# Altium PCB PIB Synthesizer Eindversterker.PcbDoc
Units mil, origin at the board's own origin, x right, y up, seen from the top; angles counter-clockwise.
Board outline 5060 x 2930 mil, 2 copper layers (Top Layer, Bottom Layer); 32 components, 26 nets, 88 pads, 1 vias.
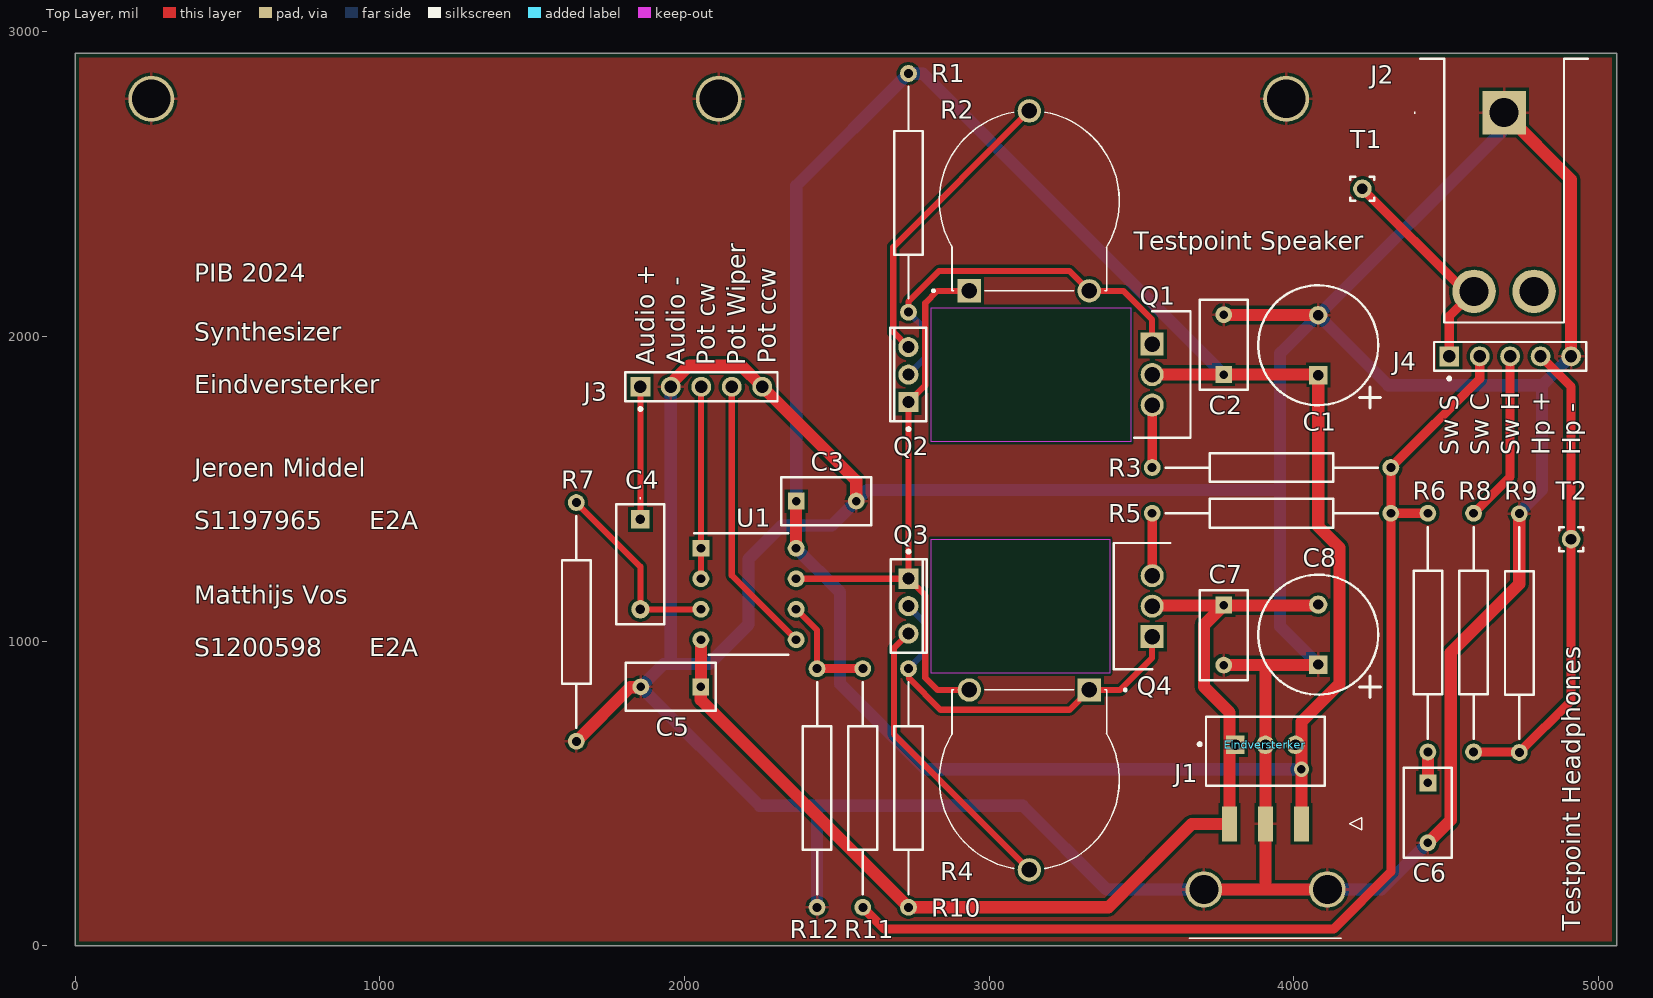
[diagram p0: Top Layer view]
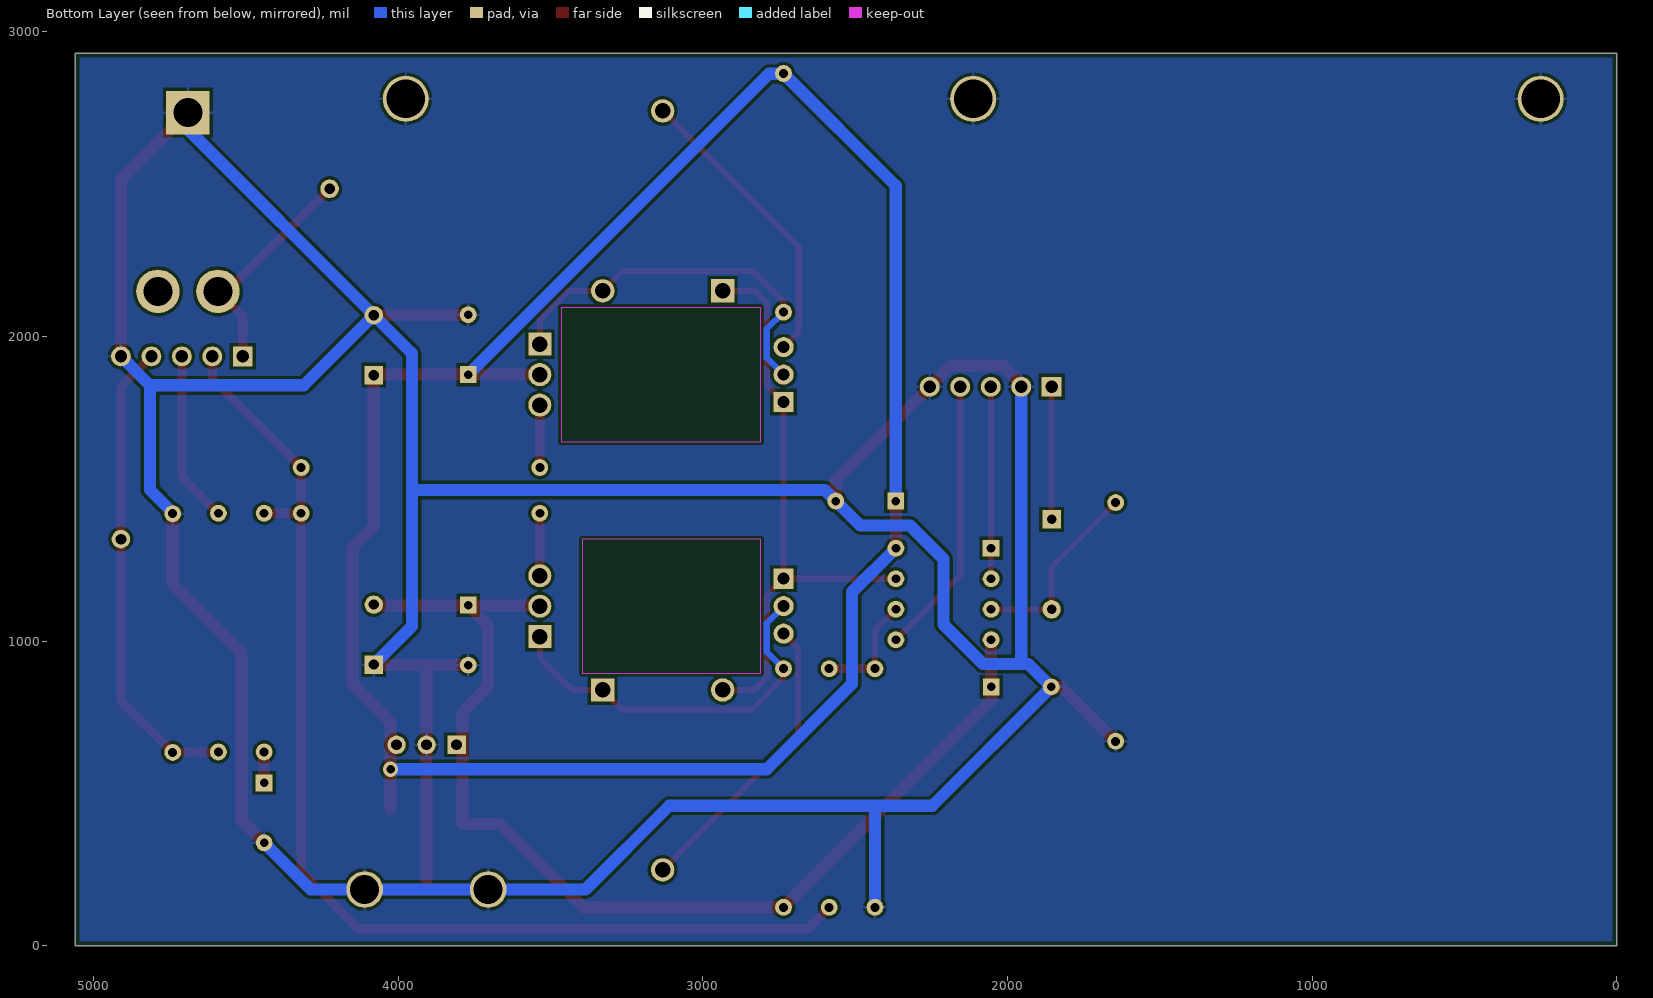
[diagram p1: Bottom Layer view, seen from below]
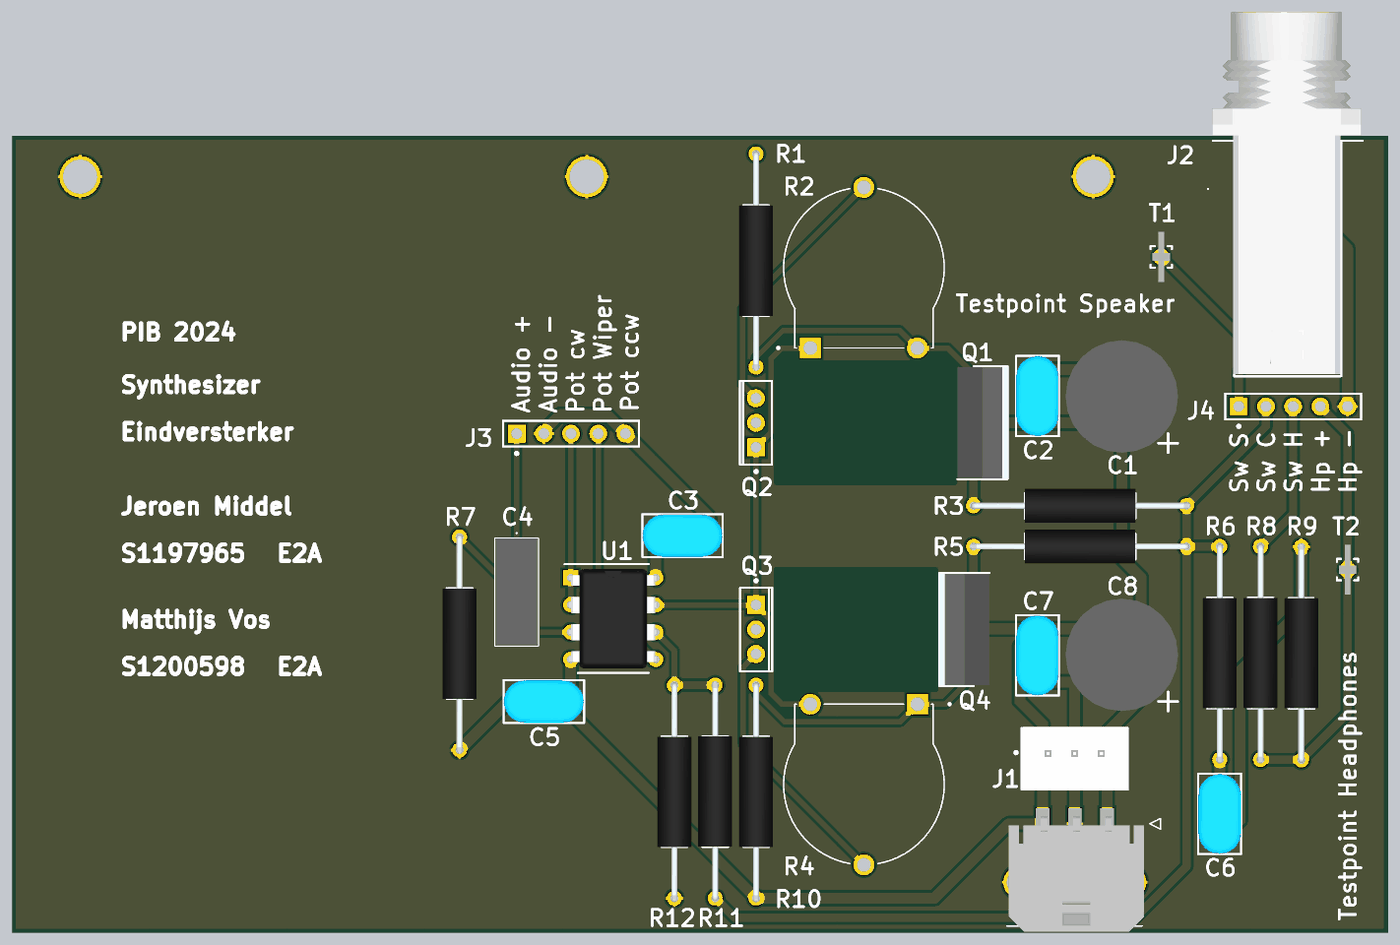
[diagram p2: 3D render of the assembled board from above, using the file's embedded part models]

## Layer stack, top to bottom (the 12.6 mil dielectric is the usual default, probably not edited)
Top Solder: solder mask 0.4, Solder Resist, Dk 3.5
Top Layer: signal copper 1.4
Dielectric 1: dielectric 12.6, FR-4, Dk 4.8
Bottom Layer: signal copper 1.4
Bottom Solder: solder mask 0.4, Solder Resist, Dk 3.5

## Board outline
0,0 0,2930 5060,2930 5060,0

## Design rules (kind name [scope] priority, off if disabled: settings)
BoardOutlineClearance "BoardOutlineClearance AISLER" [All] p1: gap=11.81 ignorepadtopadclearanceinfootprint=FALSE
Clearance [All] p1: gap=10 ignorepadtopadclearanceinfootprint=FALSE
Clearance "Clearance AISLER Simple" [All] p2: gap=5.91 ignorepadtopadclearanceinfootprint=FALSE except(0: Arc-Text Track-Text SMDPad-Text THPad-Text Via-Text Fill-Text Poly-Text Region-Text Text-Text Text-Hole; 7.87: Fill-Fill Fill-Poly Fill-Region Poly-Poly Poly-Region Region-Region; 9.84: Arc-Hole Track-Hole SMDPad-Hole THPad-Hole Via-Hole Fill-Hole Poly-Hole Region-Hole)
Height [All] p1: minheight=0 maxheight=3000 prefheight=500
HoleSize [All] p1: absolutevalues=TRUE maxlimit=220 minlimit=1 maxpercent=80.000 minpercent=20.000
HoleSize "HoleSize NPTH AISLER Simple" [PadIsPlated = 'False'] p2: absolutevalues=TRUE maxlimit=228.35 minlimit=11.81 maxpercent=80.000 minpercent=20.000
HoleSize "HoleSize PTH AISLER Simple" [All] p3: absolutevalues=TRUE maxlimit=222.44 minlimit=11.81 maxpercent=80.000 minpercent=20.000
HoleToHoleClearance "HoleToHoleClearance NPTH-NPTH AISLER" [PadIsPlated = 'False' vs PadIsPlated = 'False'] p2: gap=11.81 allowstackedmicrovias=FALSE // 0.25 + (0.05/2 + 0.05/2)
HoleToHoleClearance "HoleToHoleClearance NPTH-PTH AISLER" [PadIsPlated = 'False' vs PadIsPlated = 'True'] p3: gap=13.78 allowstackedmicrovias=FALSE // 0.25 + (0.05/2 + 0.15/2)
HoleToHoleClearance "HoleToHoleClearance Rest AISLER" [All] p4: gap=15.75 allowstackedmicrovias=FALSE // 0.25 + (0.15/2 + 0.15/2)
MinimumAnnularRing "MinimumAnnularRing AISLER" [IsVia] p1: minimumring=7.87
MinimumAnnularRing [All] p2: minimumring=12
MinimumSolderMaskSliver "MinimumSolderMaskSliver AISLER" [All] p2: minsoldermaskwidth=4.53 // AISLER enlarges all Solder Mask Openings by 20um by default, final Sliver is thus 0.075mm
PlaneClearance "PlaneClearance AISLER Simple" [All] p2: clearance=7.87
PolygonConnect [All] p1: connectstyle=Relief reliefconductorwidth=10 reliefentries=4 polygonreliefangle="90 Angle" airgapwidth=10
RoutingVias [All] p1: holewidth=28 width=50 viastyle="Through Hole" minholewidth=28 minwidth=50 maxholewidth=28 maxwidth=50
RoutingVias "RoutingVias AISLER Simple" [All] p2: holewidth=29.53 width=45.28 viastyle="Through Hole" minholewidth=11.81 minwidth=27.56 maxholewidth=39.37 maxwidth=55.12 // only minimum size relevant
SilkToSolderMaskClearance "SilkToSolderMaskClearance AISLER" [IsPad] p1: minsilkscreentomaskgap=5 clearancetoexposedcopper=TRUE
SolderMaskExpansion [All] p1: expansion=4 istentingtop=FALSE
Width [All] p1: maxlimit=40 minlimit=20 preferedwidth=40 minimp=50.000000 maximp=50.000000 favimp=50.000000
Width "Width AISLER Simple" [All] p2: maxlimit=59.06 minlimit=7.87 preferedwidth=19.68 // only min is relevant
27 further rules are at their usual default settings.

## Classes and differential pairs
component class "PIB Synthesizer Eindversterker": C1 C2 C3 C4 C5 C6 C7 C8 J1 J2 Q1 Q2 Q3 Q4 R1 R2 R3 R4 R5 R6 R7 R8 R9 R10 R11 R12 T1 T2 U1A U1B

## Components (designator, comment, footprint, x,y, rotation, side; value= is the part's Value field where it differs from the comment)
C1 "330uF" CAPPRD500W65D1000H2200 4080,1873.15 r90 top
C2 "100nF" FP-RDE4K1-MFG 3770,1973.43 r90 top
C3 "100nF" FP-RDE4K1-MFG 2465,1460 r0 top
C4 "470nF" MKS4C034702C00JSSD 1855,1400 r270 top
C5 "100nF" FP-RDE4K1-MFG 1955,850 r180 top
C6 "100nF" FP-RDE4K1-MFG 4440,436.57 r270 top
C7 "100nF" FP-RDE4K1-MFG 3770,1020 r270 top
C8 "330uF" CAPPRD500W65D1000H2200 4080,923.15 r90 top
Eindversterker "Comment" FP-B3B-XH-A_LF_SN-MFG 3906.57,639.33 r0 top
J1 "43650-0310" 43650-03YY_091011 3907.24,400.35 r0 top
J2 "speaker out" SJ63053A 4690,2735 r270 top
J3 "Comment" FCI-77311-5_V 2055,1835 r0 top
J4 "Comment" FCI-77311-5_V 4710,1935 r0 top
Q1 "IRF540N" TO254P469X1042X1967-3P 3535,1975 r270 top
Q2 "BD139" ONSC-TO-225-3-77-09 2735,1875 r180 top
Q3 "BD140" ONSC-TO-225-3-77-09 2735,1115 r0 top
Q4 "IRF9540N" TO254P469X1042X1967-3P 3535,1015 r90 top
R1 "2k2" RESAD1987W56L1031D239 2735,2080 r90 top
R2 "1k" TRIM_PTN15-E02SB20 3131.85,2445.28 r0 top
R3 "1" RESAD1987W56L1031D239 4318.46,1570 r180 top
R4 "1k" TRIM_PTN15-E02SB20 3131.85,544.72 r180 top
R5 "1" RESAD1987W56L1031D239 3535,1420 r0 top
R6 "10" RESAD1987W56L1031D239 4440,636.54 r90 top locked
R7 "68k" RESAD1987W56L1031D239 1645,671.54 r90 top
R8 "27" RESAD1987W56L1031D239 4590,636.54 r90 top
R9 "1" RESAD1987W56L1031D239 4740,1418.46 r270 top
R10 "2k2" RESAD1987W56L1031D239 2735,126.54 r90 top
R11 "2k2" RESAD1987W56L1031D239 2585,910 r270 top
R12 "1k" RESAD1987W56L1031D239 2435,126.54 r90 top
T1 "Testpoint Speaker" SAMTEC_MTMM-101-X-X-S-X 4225,2485 r0 top
T2 "Testpoint Headphones" SAMTEC_MTMM-101-X-X-S-X 4910,1335 r0 top
U1 "Comment" DIP794W53P254L959H508Q8N 2210,1155 r0 top

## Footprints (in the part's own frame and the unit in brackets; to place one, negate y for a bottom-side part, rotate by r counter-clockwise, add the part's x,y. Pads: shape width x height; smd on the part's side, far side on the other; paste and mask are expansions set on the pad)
43650-03YY_091011 [mm]
  rect 1.27x2.92 smd: 1(3,0) 2(0,0) 3(-3,0)
  round 3.062 hole 2.41: 4(5.15,-5.47) 5(-5.15,-5.47)
  silkscreen extent -6.36,-9.53 8,0.5, body extent -6.17,-10.06 6.47,0.68, height 5.71
CAPPRD500W65D1000H2200 [mm]
  rect 1.529x1.529 hole 0.85: 1(0,0)
  round 1.529 hole 0.85: 2(5,0)
  silkscreen extent -2.5,-5 7.5,5, body extent -2.75,-5.24 7.75,5.24, height 22
DIP794W53P254L959H508Q8N [mm]
  rect 1.409x1.409 hole 0.73: 1(-3.97,3.81)
  round 1.409 hole 0.73: 2(-3.97,1.27) 3(-3.97,-1.27) 4(-3.97,-3.81) 5(3.97,-3.81) 6(3.97,-1.27) 7(3.97,1.27) 8(3.97,3.81)
  silkscreen extent -4.53,-5.08 3.3,5.08, body extent -4.1,-4.64 4.1,4.64, height 4.21
FCI-77311-5_V [mm] "THD, 5-Leads, Body 12.7x2.4mm, Pitch 2.54mm"
  rect 1.652x1.652 hole 1.02: 1(-5.08,0)
  round 1.652 hole 1.02: 2(-2.54,0) 3(0,0) 4(2.54,0) 5(5.08,0)
  silkscreen extent -6.35,-1.97 6.35,1.2, body extent -6.35,-1.2 6.35,1.2, height 16.24
FP-B3B-XH-A_LF_SN-MFG [mm]
  rect 1.527x1.527 hole 0.9 paste-2539.97 mask+0: 1(-2.5,0.525)
  round 1.527 hole 0.9 paste-2539.97 mask+0: 2(0,0.525) 3(2.5,0.525)
  silkscreen extent -5.6,-2.88 4.95,2.88, body extent -5.05,-2.98 5.05,2.98, height 0.25
FP-RDE4K1-MFG [mm]
  rect 1.403x1.403 hole 0.7 paste-2539.97 mask+0: 1(-2.5,0)
  round 1.403 hole 0.7 paste-2539.97 mask+0: 2(2.5,0)
  silkscreen extent -3.75,-2 3.75,2, body extent -3.85,-2.1 3.85,2.1, height 0.25
MKS4C034702C00JSSD [mm]
  rect 1.529x1.529 hole 0.8: 1(0,0)
  round 1.529 hole 0.8: 2(7.5,0)
  silkscreen extent -1.8,-2 8.75,2, body extent -1.25,-2 8.75,2, height 9.1
ONSC-TO-225-3-77-09 [mm] "FM, 3-Leads, Body 7.8x3mm, Pitch 2.29mm"
  rect 1.676x1.676 hole 1: 1(0,2.29)
  round 1.676 hole 1: 2(0,0) 3(0,-2.29)
  silkscreen extent -1.49,-3.9 1.51,4.67, body extent -1.49,-3.9 1.51,3.9, height 13.64
RESAD1987W56L1031D239 [mm]
  round 1.404 hole 0.75: 1(0,0) 2(19.9,0)
  silkscreen extent 1.14,-1.19 18.8,1.19, body extent -0.28,-1.58 20.15,1.58, height 3.18
SAMTEC_MTMM-101-X-X-S-X [mm]
  round 1.545 hole 0.89: 01(0,0)
  silkscreen extent -1,-1 1,1
SJ63053A [mm]
  rect 3.63x3.63 hole 2.42: 1(0,0)
  round 3.63 hole 2.42: 2(14.9,-2.5) 3(14.9,2.5)
  silkscreen extent -4.5,-7.5 17.5,7, body extent -16.54,-7.04 17.31,6.86, height 13.32
TO254P469X1042X1967-3P [mm]
  rect 1.92x1.92 hole 1.28: 1(0,0)
  round 1.92 hole 1.28: 2(2.54,0) 3(5.08,0)
  silkscreen extent -2.73,-1.5 7.81,3.19, body extent -2.67,-1.5 7.75,3.19, height 18.84
TRIM_PTN15-E02SB20 [mm]
  rect 1.95x1.95 hole 1.3: 1(-5,-7.5)
  round 1.95 hole 1.3: 2(0,7.5) 3(5,-7.5)
  silkscreen extent -8.1,-7.6 7.5,7.39

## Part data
C1 C8: library part EEU-TP1V331B, "Capacitor Polarised", Manufacturer_Name=Panasonic, Mouser Part Number=667-EEU-TP1V331B
C2 C3 C5 C6 C7: library part CMP-06035-043861-1, "Ceramic Capacitor 47nF ±10% 1kV X7R Radial", Case/Package=Radial, Dielectric=X7R, Max Operating Temperature=125°C, Min Operating Temperature=-55°C, Package Quantity=500, Resistor Type=Ceramic, Tolerance=10%, Voltage Rating=1kV
C4: library part MKS4C034702C00JSSD, "Capacitor", Manufacturer_Name=WIMA, Mouser Part Number=505-MKS4C034702C00JS
J1: "Connector", Manufacturer_Name=Molex, Mouser Part Number=538-43650-0310
J2: library part SJ-63053A, "Connector", Manufacturer_Name="Same Sky", Mouser Part Number=490-SJ-63053A
Q1: "MOSFET (N-Channel)", Manufacturer_Name=Infineon
Q2: library part CMP-1048-01271-1, "Plastic Medium-Power Silicon NPN Transistor, 3-Pin TO-225, Bulk Box", Manufacturer="On Semiconductor"
Q3: library part CMP-1048-00039-1, "Plastic Medium-Power Silicon PNP Transistor, 3-Pin TO-225, Bulk Box", Manufacturer="On Semiconductor"
Q4: "MOSFET (P-Channel)", Manufacturer_Name=Infineon
R1 R3 R5 R6 R7 R8 R9 R10 R11 R12: library part RS01A1R000FE12, "Resistor", Manufacturer_Name=Vishay, Mouser Part Number=71-RS01A1R000FE12
R2 R4: library part PTN15-E02SB20, "15 mm, 2 kÎ©, Vertical, Linear, Screwdriver Shaftless Trimmer Potentiometer", Package=None
T1 T2: library part MTMM-101-X-X-S-X, "Connector Header Through Hole 1 position", Package=None

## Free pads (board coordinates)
  round 150.98 hole 125.98: 4(250,2780) 4(2112.5,2780) 4(3975,2780)

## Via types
v1: diameter 50, hole 28, Top Layer to Bottom Layer, 1 vias

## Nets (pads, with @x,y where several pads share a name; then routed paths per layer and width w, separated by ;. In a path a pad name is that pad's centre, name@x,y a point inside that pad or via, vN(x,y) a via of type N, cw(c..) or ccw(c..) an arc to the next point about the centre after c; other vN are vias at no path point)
+3v3: 
+5: 
+12: 
-12: 
-VCC: C5.1 C7.1 C8.2 Eindversterker.1 J1.3 Q4.2 R10.1 U1.4 | length 3644.7
  Top Layer w40: 2053.27,808.27 2053.43,808.11 ; C5.1 2053.43,808.11 ; C5.1@2053.7,850.28 U1.4 ; R10.1 2053.43,808.11 ; R10.1@2736.43,126.54 3391.54,126.54 3665,400 3789.13,400 3789.13,710.56 3789.13,766.44 3705,850.57 3705,1053.43 3769.07,1117.5 Q4.2@3537.5,1117.5 ; C7.1@3770,1117.5 C8.2@4077.5,1117.5
GND: C1.2 C2.2 C3.2 C5.2 C6.2 C7.2 C8.1 Eindversterker.2 J1.2 J1.4 J1.5 J2.1 J3.2 J3.5 J4.5 pad.4 R7.1 R9.1 R12.1 | length 15240.4
  Top Layer w40: R7.1 1822.08,848.61 1855.19,848.61 C5.2 ; J3.2 1955,1840.69 1965.51,1851.2 1965.51,1855.51 2015,1905 2185,1905 J3.5 2563.43,1526.57 C3.2 ; J1.5@3698.21,185 3907.24,185 ; C7.2 3905,921.57 C8.1@4078.43,921.57 ; C2.2@3770.93,2070.93 C1.2@4079.07,2070.93 ; 3907.24,919.33 3907.24,450.35 J1.2 3907.24,185 ; J1.4@4100.1,185 3907.24,185 ; C6.2 4515,413.15 4515,962.63 4740,1187.63 R9.1 ; J2.1 4910,2515 J4.5
  Bottom Layer w40: J3.2 1955,925 ; R12.1 2435,460 ; C8.1 3955,1048.15 3955,1496.57 ; C6.2 4286.85,185 J1.4 J1.5 3385,185 3110,460 2435,460 ; J2.1 4690,2680 C1.2 ; R9.1@4740,1421.96 4815,1496.96 4815,1840 ; J4.5 4815,1840 ; 1955,925 2080,925 2210,1055 2210,1270 2320,1380 2483.43,1380 2600,1496.57 3955,1496.57 ; 1955,925 1931.57,925 C5.2 2246.57,460 2435,460 ; 3955,1496.57 3955,1945 C1.2 ; C1.2 4310,1840 4815,1840
NetBR1_2: 
NetC4_1: C4.1 J3.1 | length 440.9
  Top Layer w20: J3.1 1855,1415.28 C4.1@1870,1400.28
NetC4_2: C4.2 R7.2 U1.3 | length 635.7
  Top Layer w20: R7.2 1855,1245 C4.2 U1.3@2053.43,1104.72
NetC6_1: C6.1 R6.1 | length 101.5
  Top Layer w40: C6.1 R6.1
NetJ2_2: J2.2 J4.1 T1.01 | length 723.2
  Top Layer w30: T1.01 J2.2@4561.61,2148.39 ; J4.1 4510,2066.81 J2.2
NetJ4_3: J4.4 R8.1 R9.2 T2.01 | length 1563.7
  Top Layer w20: R8.1 R8.1@4590,639.9
  Top Layer w30: R8.1@4590.77,635.77 R9.2@4739.23,635.77 ; R9.2 4910,805 T2.01 4910,1835 J4.4
NetJ8_1: 
NetQ1_G: Q1.1 Q2.2 R1.1 R2.3 | length 1273.5
  Top Layer w20: R1.1 2734.72,2080.28 2734.72,2114.72 2835,2215 3263.7,2215 R2.3 3440,2150 3535,2055 Q1.1
  Bottom Layer w20: Q2.2 2790,1930 2790,2025 R1.1
NetQ1_S: Q1.3 R3.2 | length 205
  Top Layer w30: R3.2 Q1.3
NetQ2_B: Q2.3 R2.2 | length 980.9
  Top Layer w20: Q2.3@2735,1965.42 2685,2015.42 2685,2293.7 R2.2
NetQ2_E: Q2.1 Q3.1 R2.1 R4.3 U1.7 | length 1967.2
  Top Layer w20: U1.7 Q3.1@2734.84,1205 ; R4.3 2830,840 2790,880 2790,1150.16 Q3.1 Q2.1 2790,1839.84 2790,2110 2830,2150 R2.1
NetQ3_B: Q3.3 R4.2 | length 979.2
  Top Layer w20: Q3.3 2687.36,977.2 2687.36,693.94 R4.2
NetQ3_C: Q3.2 Q4.1 R4.1 R10.2 | length 1263.7
  Top Layer w20: R10.2 2737.22,907.78 2737.22,877.78 2840,775 3263.7,775 R4.1 3430,840 3535,945 Q4.1
  Bottom Layer w20: R10.2 2790,965 2790,1059.18 Q3.2@2735,1114.18
NetQ4_S: Q4.3 R5.1 | length 205
  Top Layer w30: Q4.3 R5.1
NetR3_1: J4.2 R3.1 R5.2 R6.2 R11.2 | length 3775
  Top Layer w25: R11.2 R11.2@2588.88,122.66
  Top Layer w30: R11.2@2588.88,122.66 2656.54,55 4130,55 4318.46,243.46 R5.2 ; R6.2 R5.2 ; J4.2 4610,1861.54 R3.1 R5.2
NetR8_2: J4.3 R8.2 | length 564.7
  Top Layer w30: R8.2 4710,1540 J4.3
NetR11_1: R11.1 R12.2 U1.6 | length 373.5
  Top Layer w20: U1.6 2435,1036.3 R12.2
  Top Layer w30: R12.2 R11.1
NetU1A_1: J3.3 U1.1 U1.2 | length 631.5
  Top Layer w20: J3.3@2050,1835 2053.7,1831.3 U1.1 U1.2
NetU1B_2: J3.4 U1.5 | length 917.5
  Top Layer w20: J3.4 2155,1216.3 U1.5
VCC: C1.1 C2.1 C3.1 Eindversterker.3 J1.1 Q1.2 R1.2 U1.8 | length 7335.5
  Top Layer w40: U1.8 C3.1@2366.3,1459.72 ; Q1.2 C2.1 C1.1@4078.15,1875 ; J1.1@4025.35,450.35 4025.35,735.35 4150,860 4150,1306.71 4080,1376.71 C1.1
  Bottom Layer w40: U1.8 2510,1161.3 2510,860 2790,580 v1(4025,580) ; C3.1 2366.57,2495.04 R1.2 ; R1.2@2737.44,2863.46 2737.44,2862.46 2782.54,2862.46 C2.1
pads on no net: J2.3

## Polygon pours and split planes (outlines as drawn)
GND on Bottom Layer "GND_L02_P000" (solid, pour order 0): 15,2915 15,15 5045,15 5045,2870 5045,2890 5045,2915
GND on Top Layer "GND_L01_P001" (solid, pour order 1): 13.44,2915 13.44,15 5043.44,15 5043.44,2870 5043.44,2890 5043.44,2915

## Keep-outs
Keep-Out Layer:
  region: 3395,1335 3395,895 2810,895 2810,1335
  region: 3465,2095 3465,1655 2810,1655 2810,2095

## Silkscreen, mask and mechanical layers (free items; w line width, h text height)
Top Overlay:
  lines w10: 4215,850 4285,850 ; 4215,1800 4285,1800 ; 4250,815 4250,885 ; 4250,1765 4250,1835
  text "PIB 2024" at 390,2180 h60
  text "Synthesizer" at 390,1986.67 h60
  text "Pot ccw" at 2300,1910 h60 r90
  text "Audio +" at 1900,1905 h60 r90
  text "Audio -" at 2000,1905 h60 r90
  text "Pot cw" at 2100,1905 h60 r90
  text "Pot Wiper" at 2200.01,1905 h60 r90
  text "Eindversterker" at 390,1813.34 h60
  text "Sw S" at 4540,1610 h60 r90
  text "Sw C" at 4639.99,1610 h60 r90
  text "Sw H" at 4739.98,1610 h60 r90
  text "Hp +" at 4839.96,1610 h60 r90
  text "Hp -" at 4939.94,1610 h60 r90
  text "Jeroen Middel" at 390,1540 h60
  text "S1197965" at 390,1366.66 h60
  text "E2A" at 965,1366.66 h60
  text "Matthijs Vos" at 390,1123.34 h60
  text "S1200598" at 390,950 h60
  text "E2A" at 965,950 h60
Mechanical 1:
  the board outline again, w10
